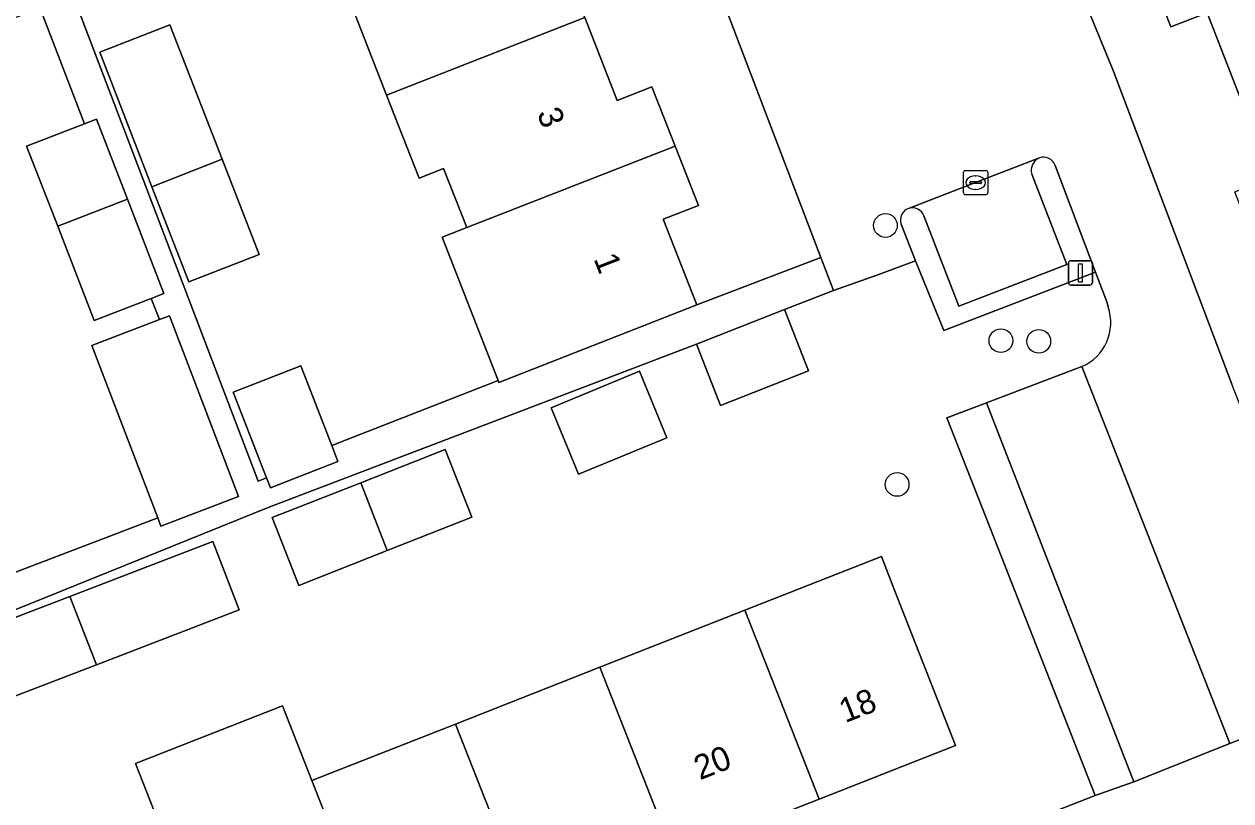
# Model space of a CAD drawing. Extents: x 159680 to 160786, y 387323 to 388340.
# Drawn here: x 160019.77 to 160069.54, y 387767.08 to 387799.1 of the extents above; entities that cross this region are included whole.
import ezdxf

# ---------------------------------------------------------------- set-up
doc = ezdxf.new("R2010")
doc.units = 0
for name, color, linetype in [('IMGEO_Boom', 7, 'Continuous'), ('IMGEO_Erf', 7, 'Continuous'), ('IMGEO_Kolk', 7, 'Continuous'), ('IMGEO_Lichtmast', 7, 'Continuous'), ('IMGEO_Pand', 7, 'Continuous'), ('IMGEO_Pand_nummerreeks', 7, 'Continuous'), ('IMGEO_Parkeervlak_open', 7, 'Continuous'), ('IMGEO_Verkeerseiland_open', 7, 'Continuous'), ('IMGEO_Voetpad_open', 7, 'Continuous'), ('IMGEO_Woonerf_open', 7, 'Continuous')]:
    doc.layers.add(name, color=color, linetype=linetype)

msp = doc.modelspace()

# ---------------------------------------------------------------- linework, layer by layer
at = {"layer": 'IMGEO_Boom'}
for centre in [(160055.296, 387790.798), (160060.058, 387786.047), (160061.623, 387786.023), (160055.778, 387780.121)]:
    msp.add_circle(centre, 0.489, dxfattribs=at)
at = {"layer": 'IMGEO_Erf'}
for points in [[(160056.188, 387831.428), (160054.866, 387834.832), (160053.363, 387834.249), (160052.404, 387836.718), (160051.446, 387839.184), (160052.908, 387839.752), (160051.529, 387843.301), (160047.288, 387841.646), (160061.542, 387805.11), (160062.97, 387801.379), (160063.697, 387799.597), (160064.692, 387797.183), (160069.582, 387784.252)], [(160072.059, 387783.33), (160074.487, 387784.277), (160073.099, 387787.852), (160071.614, 387787.275), (160070.66, 387789.732), (160069.706, 387792.188), (160071.205, 387792.77), (160069.885, 387796.17), (160068.564, 387799.57), (160067.07, 387798.99), (160066.106, 387801.47)], [(160021.808, 387800.245), (160029.428, 387780.26), (160029.771, 387780.394), (160028.396, 387783.928), (160031.184, 387785.012), (160032.461, 387781.727), (160039.32, 387784.409), (160037.01, 387790.316), (160038.027, 387790.713), (160037.076, 387793.143), (160036.06, 387792.745), (160034.718, 387796.174), (160033.38, 387799.594)], [(160018.878, 387776.295), (160025.281, 387778.75), (160022.561, 387785.844), (160025.355, 387786.915), (160025.019, 387787.793), (160022.661, 387786.88), (160021.157, 387790.765), (160019.877, 387794.073), (160022.259, 387794.994), (160020.44, 387799.739), (160018.804, 387799.133)], [(160042.894, 387799.368), (160044.229, 387795.955), (160045.669, 387796.518), (160046.626, 387794.072), (160047.582, 387791.627), (160046.135, 387791.061), (160047.518, 387787.525), (160052.63, 387789.479), (160048.749, 387799.635)], [(160064.479, 387787.442), (160064.427, 387787.645), (160063.962, 387788.871), (160057.706, 387786.471), (160056.534, 387789.34), (160054.983, 387788.763), (160053.15, 387788.119), (160051.14, 387787.332), (160052.129, 387784.803), (160048.494, 387783.38), (160047.504, 387785.909), (160029.842, 387779.175), (160013.399, 387772.535), (160014.444, 387769.949), (160010.862, 387768.501), (160009.817, 387771.087), (160007.01, 387769.993), (160014.804, 387750)], [(160059.933, 387777.515), (160057.826, 387782.871), (160059.459, 387783.492), (160063.399, 387784.981)], [(160017.309, 387749.053), (160019.73, 387750), (160063.953, 387767.299), (160059.933, 387777.515)]]:
    msp.add_lwpolyline(points, dxfattribs=at)
for points in [[(160027.94, 387793.526), (160029.467, 387789.595), (160026.569, 387788.469), (160025.044, 387792.395), (160022.891, 387797.939), (160025.789, 387799.064)], [(160041.511, 387783.286), (160045.155, 387784.787), (160046.284, 387782.045), (160042.641, 387780.544)], [(160034.753, 387777.4), (160031.105, 387775.96), (160030.003, 387778.753), (160033.655, 387780.194), (160037.133, 387781.567), (160038.235, 387778.775)], [(160022.762, 387772.689), (160019.107, 387771.287), (160018.024, 387774.111), (160021.655, 387775.504), (160027.562, 387777.77), (160028.645, 387774.946)], [(160049.502, 387774.936), (160055.131, 387777.149), (160055.649, 387775.831), (160058.192, 387769.361), (160052.563, 387767.148), (160046.577, 387764.795), (160040.627, 387762.457), (160034.706, 387760.129), (160028.636, 387757.743), (160023.011, 387755.532), (160016.854, 387753.112), (160013.793, 387760.899), (160019.95, 387763.319), (160025.575, 387765.531), (160024.363, 387768.614), (160030.432, 387770.999), (160031.644, 387767.916), (160037.566, 387770.244), (160043.515, 387772.583)]]:
    msp.add_lwpolyline(points, close=True, dxfattribs=at)
msp.add_arc((160062.625, 387786.788), 1.966, 293.1952, 19.4167, dxfattribs=at)
at = {"layer": 'IMGEO_Kolk'}
for p, q in [((160058.516, 387792.14), (160058.516, 387792.992)), ((160058.591, 387793.066), (160059.443, 387793.066)), ((160059.004, 387792.846), (160059.029, 387792.846)), ((160059.517, 387792.992), (160059.517, 387792.14)), ((160058.775, 387792.56), (160058.775, 387792.572)), ((160059.213, 387792.523), (160058.815, 387792.523)), ((160058.818, 387792.609), (160059.216, 387792.609)), ((160059.027, 387792.286), (160059.002, 387792.286)), ((160059.259, 387792.572), (160059.259, 387792.56)), ((160059.443, 387792.066), (160058.591, 387792.066))]:
    msp.add_line(p, q, dxfattribs=at)
for points in [[(160058.516, 387792.14), (160058.516, 387792.992)], [(160058.591, 387793.066), (160059.443, 387793.066)], [(160059.517, 387792.992), (160059.517, 387792.14)], [(160059.443, 387792.066), (160058.591, 387792.066)]]:
    msp.add_lwpolyline(points, dxfattribs=at)
for centre, radius, start, end in [((160058.593, 387792.99), 0.0765, 91.552, 178.448), ((160058.593, 387792.99), 0.0765, 91.552, 178.448), ((160059.441, 387792.99), 0.0765, 1.552, 88.448), ((160059.441, 387792.99), 0.0765, 1.552, 88.448), ((160058.815, 387792.569), 0.0403, 85.8775, 175.7526), ((160058.812, 387792.559), 0.0366, 178.938, 274.7102), ((160059.216, 387792.566), 0.043, 264.8664, 352.4533), ((160059.22, 387792.571), 0.0386, 1.7309, 96.639), ((160058.593, 387792.142), 0.0765, 181.552, 268.448), ((160058.593, 387792.142), 0.0765, 181.552, 268.448), ((160059.441, 387792.142), 0.0765, 271.552, 358.448), ((160059.441, 387792.142), 0.0765, 271.552, 358.448)]:
    msp.add_arc(centre, radius, start, end, dxfattribs=at)
for centre, major_axis, ratio, start_param, end_param in [((160059.003, 387792.566), (-0.387, 0.002), 0.722429, 4.712389, 7.853982), ((160059.028, 387792.566), (-0.39, 0.002), 0.717154, 1.570796, 4.712389)]:
    msp.add_ellipse(centre, major_axis=major_axis, ratio=ratio, start_param=start_param, end_param=end_param, dxfattribs=at)
at = {"layer": 'IMGEO_Lichtmast'}
for p, q in [((160062.842, 387788.442), (160062.842, 387789.242)), ((160062.842, 387789.242), (160062.842, 387788.442)), ((160062.942, 387789.342), (160063.732, 387789.342)), ((160063.732, 387789.342), (160062.942, 387789.342)), ((160063.832, 387789.242), (160063.832, 387788.442)), ((160063.832, 387788.442), (160063.832, 387789.242)), ((160063.732, 387788.342), (160062.942, 387788.342)), ((160062.942, 387788.342), (160063.732, 387788.342))]:
    msp.add_line(p, q, dxfattribs=at)
msp.add_lwpolyline([(160063.262, 387789.217), (160063.412, 387789.217), (160063.412, 387788.467), (160063.262, 387788.467), (160063.262, 387789.217)], dxfattribs=at)
for centre, start, end in [((160062.942, 387789.242), 90, 180), ((160062.942, 387789.242), 90, 180), ((160063.732, 387789.242), 0, 90), ((160063.732, 387789.242), 360, 90), ((160062.942, 387788.442), 180, 270), ((160062.942, 387788.442), 180, 270), ((160063.732, 387788.442), 270, 0), ((160063.732, 387788.442), 270, 0)]:
    msp.add_arc(centre, 0.1, start, end, dxfattribs=at)
at = {"layer": 'IMGEO_Pand'}
for points in [[(160042.058, 387805.785), (160033.446, 387802.421), (160034.397, 387799.991), (160033.38, 387799.594), (160034.718, 387796.174), (160042.894, 387799.368), (160041.559, 387802.782), (160043.011, 387803.35)], [(160075.774, 387805.231), (160074.758, 387804.836), (160066.106, 387801.47), (160067.07, 387798.99), (160068.564, 387799.57), (160069.885, 387796.17), (160078.059, 387799.35)], [(160042.894, 387799.368), (160034.718, 387796.174), (160036.06, 387792.745), (160037.076, 387793.143), (160038.027, 387790.713), (160046.626, 387794.072), (160045.669, 387796.518), (160044.229, 387795.955)], [(160025.044, 387792.395), (160027.94, 387793.526), (160025.789, 387799.064), (160022.891, 387797.939)], [(160022.752, 387795.185), (160022.259, 387794.994), (160019.877, 387794.073), (160021.157, 387790.765), (160024.03, 387791.883)], [(160046.135, 387791.061), (160047.582, 387791.627), (160046.626, 387794.072), (160038.027, 387790.713), (160037.01, 387790.316), (160039.32, 387784.409), (160039.351, 387784.33), (160042.862, 387785.704), (160047.518, 387787.525)], [(160027.94, 387793.526), (160025.044, 387792.395), (160026.569, 387788.469), (160029.467, 387789.595)], [(160024.03, 387791.883), (160021.157, 387790.765), (160022.661, 387786.88), (160025.019, 387787.793), (160025.536, 387787.993)], [(160051.14, 387787.332), (160047.504, 387785.909), (160048.494, 387783.38), (160052.129, 387784.803)], [(160025.766, 387787.073), (160025.355, 387786.915), (160022.561, 387785.844), (160025.281, 387778.75), (160025.416, 387778.398), (160028.62, 387779.626)], [(160031.184, 387785.012), (160028.396, 387783.928), (160029.771, 387780.394), (160029.929, 387779.988), (160032.716, 387781.072), (160032.461, 387781.727)], [(160045.155, 387784.787), (160041.511, 387783.286), (160042.641, 387780.544), (160046.284, 387782.045)], [(160033.655, 387780.194), (160034.753, 387777.4), (160038.235, 387778.775), (160037.133, 387781.567)], [(160034.753, 387777.4), (160033.655, 387780.194), (160030.003, 387778.753), (160031.105, 387775.96)], [(160021.655, 387775.504), (160022.762, 387772.689), (160028.645, 387774.946), (160027.562, 387777.77)], [(160052.563, 387767.148), (160058.192, 387769.361), (160055.649, 387775.831), (160055.131, 387777.149), (160049.502, 387774.936)], [(160022.762, 387772.689), (160021.655, 387775.504), (160018.024, 387774.111), (160019.107, 387771.287)], [(160049.502, 387774.936), (160043.515, 387772.583), (160046.577, 387764.795), (160052.563, 387767.148)], [(160040.627, 387762.457), (160046.577, 387764.795), (160043.515, 387772.583), (160037.566, 387770.244)], [(160031.644, 387767.916), (160030.432, 387770.999), (160024.363, 387768.614), (160025.575, 387765.531), (160028.636, 387757.743), (160034.706, 387760.129)], [(160034.706, 387760.129), (160040.627, 387762.457), (160037.566, 387770.244), (160031.644, 387767.916)]]:
    msp.add_lwpolyline(points, close=True, dxfattribs=at)
at = {"layer": 'IMGEO_Parkeervlak_open'}
for points in [[(160061.645, 387793.588), (160059.017, 387792.566), (160056.247, 387791.501)], [(160056.883, 387791.195), (160058.318, 387787.478), (160062.781, 387789.194), (160061.332, 387792.917)]]:
    msp.add_lwpolyline(points, dxfattribs=at)
msp.add_lwpolyline([(160063.399, 387784.981), (160059.459, 387783.492), (160065.547, 387767.865), (160069.507, 387769.439)], close=True, dxfattribs=at)
for centre, radius, start, end in [((160061.878, 387793.071), 0.567, 114.225, 195.7599), ((160056.407, 387791.02), 0.507, 20.1534, 108.4592)]:
    msp.add_arc(centre, radius, start, end, dxfattribs=at)
at = {"layer": 'IMGEO_Verkeerseiland_open'}
for points in [[(160055.952, 387790.852), (160056.534, 387789.34), (160057.706, 387786.471), (160063.962, 387788.871), (160062.294, 387793.271)], [(160061.332, 387792.917), (160062.781, 387789.194), (160058.318, 387787.478), (160056.883, 387791.195)]]:
    msp.add_lwpolyline(points, dxfattribs=at)
for centre, radius, start, end in [((160061.878, 387793.071), 0.567, 114.225, 195.7599), ((160061.81, 387793.102), 0.513, 19.2075, 108.7267), ((160056.414, 387791.034), 0.496, 109.6285, 201.4836), ((160056.407, 387791.02), 0.507, 20.1534, 108.4592)]:
    msp.add_arc(centre, radius, start, end, dxfattribs=at)
at = {"layer": 'IMGEO_Voetpad_open'}
for points in [[(160180.841, 387812.88), (160130.55, 387793.293), (160129.926, 387793.044), (160125.07, 387791.096), (160119.932, 387789.037), (160079.601, 387773.37), (160078.884, 387773.091), (160074.62, 387771.435), (160069.507, 387769.439), (160065.547, 387767.865), (160063.953, 387767.299), (160019.73, 387750), (160017.309, 387749.053)], [(160013.399, 387772.535), (160029.842, 387779.175), (160047.504, 387785.909), (160051.14, 387787.332), (160053.15, 387788.119), (160052.63, 387789.479), (160047.518, 387787.525), (160042.862, 387785.704), (160039.351, 387784.33), (160039.32, 387784.409), (160032.461, 387781.727), (160032.716, 387781.072), (160029.929, 387779.988), (160029.771, 387780.394), (160029.428, 387780.26), (160021.808, 387800.245)], [(160020.44, 387799.739), (160022.259, 387794.994), (160022.752, 387795.185), (160024.03, 387791.883), (160025.536, 387787.993), (160025.019, 387787.793), (160025.355, 387786.915), (160025.766, 387787.073), (160028.62, 387779.626), (160025.416, 387778.398), (160025.281, 387778.75), (160018.878, 387776.295)]]:
    msp.add_lwpolyline(points, dxfattribs=at)
msp.add_lwpolyline([(160059.459, 387783.492), (160057.826, 387782.871), (160059.933, 387777.515), (160063.953, 387767.299), (160065.547, 387767.865)], close=True, dxfattribs=at)
at = {"layer": 'IMGEO_Woonerf_open'}
for points in [[(160051.759, 387801.571), (160051.362, 387802.608), (160048.124, 387801.362), (160048.749, 387799.635), (160052.63, 387789.479), (160053.15, 387788.119), (160054.983, 387788.763), (160056.534, 387789.34), (160055.952, 387790.852)], [(160063.399, 387784.981), (160069.507, 387769.439), (160074.62, 387771.435), (160069.582, 387784.252), (160064.692, 387797.183), (160063.697, 387799.597), (160063.506, 387799.505)], [(160056.247, 387791.501), (160059.017, 387792.566), (160061.645, 387793.588)], [(160062.294, 387793.271), (160063.962, 387788.871), (160064.427, 387787.645), (160064.479, 387787.442)]]:
    msp.add_lwpolyline(points, dxfattribs=at)
for centre, radius, start, end in [((160061.81, 387793.102), 0.513, 19.2075, 108.7267), ((160056.414, 387791.034), 0.496, 109.6285, 201.4836), ((160062.625, 387786.788), 1.966, 293.1952, 19.4167)]:
    msp.add_arc(centre, radius, start, end, dxfattribs=at)

# ---------------------------------------------------------------- texts
at = {"layer": 'IMGEO_Pand_nummerreeks'}
for s, rotation, p in [('3', 291.3367, (160040.91, 387795.428)), ('1', 291.3367, (160043.253, 387789.428)), ('18', 21.4586, (160053.635, 387770.277)), ('20', 21.4586, (160047.646, 387767.923))]:
    msp.add_text(s, height=1, rotation=rotation, dxfattribs=at).set_placement(p)

doc.saveas('drawing.dxf')
